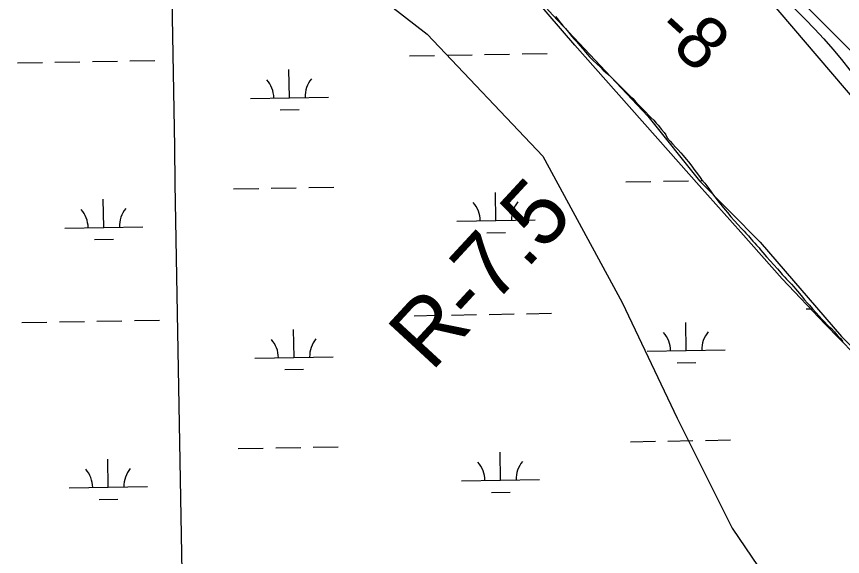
# Model space of a CAD drawing. Extents: x 3903937 to 3942190, y 260677 to 286651.
# Drawn here: x 3923778 to 3924835, y 275569 to 276260 of the extents above; entities that cross this region are included whole.
import ezdxf

# ---------------------------------------------------------------- set-up
doc = ezdxf.new("R2010")
doc.units = 0
for name, color, linetype in [('V-GRID-MAJR', 7, 'Continuous'), ('V-RIVR-EDGE', 7, 'Continuous'), ('V-RIVR-RANG', 7, 'Continuous'), ('V-RIVR-RANG-IDEN', 7, 'Continuous'), ('V-RRAP-FSHR', 7, 'Continuous'), ('V-SITE-VEGE', 7, 'Continuous'), ('V-TOPO-DPTH', 7, 'Continuous'), ('V-TOPO-MINR', 7, 'Continuous'), ('V-WETL-SWMP', 7, 'Continuous')]:
    doc.layers.add(name, color=color, linetype=linetype)

msp = doc.modelspace()

# ---------------------------------------------------------------- linework, layer by layer
at = {"layer": 'V-GRID-MAJR'}
msp.add_spline([(3924152.694, 266296.911), (3924046.094, 272353.359), (3923939.434, 278413.279), (3923832.773, 284473.19), (3923832.7120000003, 284476.667)], degree=3, dxfattribs=at)
at = {"layer": 'V-RIVR-EDGE'}
msp.add_lwpolyline([(3923809.041392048, 277077.51291171), (3923934.9847806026, 276930.5789583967), (3924022.0956243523, 276825.6261346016), (3924100.8102421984, 276726.9704802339), (3924229.9022154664, 276553.79832097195), (3924320.1616439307, 276432.0530453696), (3924352.6970193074, 276398.4681417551), (3924369.4894711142, 276368.03182285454), (3924377.885697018, 276353.33842752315), (3924399.9257900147, 276333.39739100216), (3924463.9470125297, 276262.0294708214), (3924585.692288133, 276132.93749755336), (3924651.8125671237, 276050.02476675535), (3924729.477656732, 275971.3101489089), (3924833.3809522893, 275850.6144015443), (3924912.0955701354, 275772.9493119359), (3925056.9304669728, 275630.21347157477), (3925314.0648852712, 275376.22763799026)], dxfattribs=at)
at = {"layer": 'V-RRAP-FSHR'}
msp.add_lwpolyline([(3924868.6260422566, 275809.15788427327), (3924812.6111942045, 275866.2745563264), (3924757.724794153, 275924.4418523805), (3924704.6262981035, 275984.2803164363), (3924651.527802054, 276044.11878049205), (3924598.431354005, 276103.95724454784), (3924545.3328579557, 276163.7957086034), (3924492.2343619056, 276223.6341726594), (3924439.8751938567, 276284.96972471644), (3924389.62136981, 276346.34214077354), (3924339.367545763, 276408.58905283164), (3924289.1137217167, 276470.83596488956), (3924238.8598976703, 276533.79967694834), (3924188.6060736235, 276595.3256930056), (3924138.3522495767, 276657.57260506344), (3924088.86028153, 276719.80722912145), (3924037.8015934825, 276782.28966117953), (3923987.5150014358, 276844.2498532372), (3923937.232505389, 276906.4701412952), (3923886.9479613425, 276968.6924773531), (3923836.661369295, 277030.91276541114), (3923777.9144892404, 277084.7342054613)], dxfattribs=at)
at = {"layer": 'V-SITE-VEGE'}
for p, q in [((3924123.8340000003, 276378.223), (3924303.3000000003, 276237.702)), ((3924303.3000000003, 276237.702), (3924451.557, 276081.56200000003)), ((3924451.557, 276081.56200000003), (3924552.9960000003, 275894.199)), ((3924552.9960000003, 275894.199), (3924623.222, 275745.869)), ((3924623.222, 275745.869), (3924693.448, 275605.34499999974)), ((3924693.448, 275605.34499999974), (3924810.494, 275433.594))]:
    msp.add_line(p, q, dxfattribs=at)
at = {"layer": 'V-TOPO-DPTH'}
for points in [[(3923865.174726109, 277116.27481425), (3923945.7666094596, 277041.54291989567), (3924026.2410626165, 276966.68508159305), (3924106.539370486, 276891.6383273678), (3924186.720248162, 276816.4656291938), (3924428.1951694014, 276589.5397381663), (3924477.5856964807, 276542.7901825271), (3924526.750617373, 276495.8062376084), (3924575.5771289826, 276448.47070877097), (3924624.178034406, 276400.90079065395), (3924719.8113720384, 276306.62193106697), (3924721.0372647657, 276305.40519470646), (3924721.64690651, 276304.79351949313), (3924722.2548959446, 276304.1801907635), (3924727.854134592, 276298.50879869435), (3924730.4768868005, 276295.7084617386), (3924731.727843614, 276294.25462085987), (3924734.086898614, 276291.2362584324), (3924736.08815973, 276287.99108001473), (3924736.9511130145, 276286.2835869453), (3925453.180204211, 275446.62080505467)], [(3925522.551794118, 275441.304044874), (3924958.2296571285, 276088.6577581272), (3924936.4956570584, 276115.5661055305), (3924914.136955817, 276141.944487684), (3924891.2998223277, 276167.8897105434), (3924867.745040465, 276193.1851944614), (3924843.711826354, 276218.04751908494), (3924757.4314059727, 276304.83790498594), (3924747.84406271, 276314.4520852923), (3924738.2369359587, 276324.04639421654), (3924728.6001339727, 276333.61089606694), (3924718.943548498, 276343.15552653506), (3924144.81338033, 276908.8740663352), (3924099.7941607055, 276953.09772132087), (3924054.6847673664, 276997.2289203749), (3924009.440113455, 277041.2214355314), (3923964.105285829, 277085.12149475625)], [(3923964.105285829, 277085.12149475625), (3924009.440113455, 277041.2214355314), (3924054.6847673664, 276997.2289203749), (3924099.7941607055, 276953.09772132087), (3924144.81338033, 276908.8740663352), (3924718.943548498, 276343.15552653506), (3924728.6001339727, 276333.61089606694), (3924738.2369359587, 276324.04639421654), (3924747.84406271, 276314.4520852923), (3924757.4314059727, 276304.83790498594), (3924843.711826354, 276218.04751908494), (3924867.745040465, 276193.1851944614), (3924891.2998223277, 276167.8897105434), (3924914.136955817, 276141.944487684), (3924936.4956570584, 276115.5661055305), (3924958.2296571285, 276088.6577581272), (3925522.551794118, 275441.304044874)]]:
    msp.add_lwpolyline(points, dxfattribs=at)
at = {"layer": 'V-TOPO-MINR'}
for points in [[(3923865.174726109, 277116.27481425), (3923945.7666094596, 277041.54291989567), (3924026.2410626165, 276966.68508159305), (3924106.539370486, 276891.6383273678), (3924186.720248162, 276816.4656291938), (3924428.1951694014, 276589.5397381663), (3924477.5856964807, 276542.7901825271), (3924526.750617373, 276495.8062376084), (3924575.5771289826, 276448.47070877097), (3924624.178034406, 276400.90079065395), (3924719.8113720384, 276306.62193106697), (3924721.0372647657, 276305.40519470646), (3924721.64690651, 276304.79351949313), (3924722.2548959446, 276304.1801907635), (3924727.854134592, 276298.50879869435), (3924730.4768868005, 276295.7084617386), (3924731.727843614, 276294.25462085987), (3924734.086898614, 276291.2362584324), (3924736.08815973, 276287.99108001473), (3924736.9511130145, 276286.2835869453), (3925453.180204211, 275446.62080505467)], [(3923964.105285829, 277085.12149475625), (3924009.440113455, 277041.2214355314), (3924054.6847673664, 276997.2289203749), (3924099.7941607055, 276953.09772132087), (3924144.81338033, 276908.8740663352), (3924718.943548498, 276343.15552653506), (3924728.6001339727, 276333.61089606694), (3924738.2369359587, 276324.04639421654), (3924747.84406271, 276314.4520852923), (3924757.4314059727, 276304.83790498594), (3924843.711826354, 276218.04751908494), (3924867.745040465, 276193.1851944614), (3924891.2998223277, 276167.8897105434), (3924914.136955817, 276141.944487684), (3924936.4956570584, 276115.5661055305), (3924958.2296571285, 276088.6577581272), (3925522.551794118, 275441.304044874)], [(3923968.4715438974, 277067.63885066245), (3923988.589107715, 277047.81587338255), (3924719.3890937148, 276325.1749291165), (3924724.581696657, 276320.02429766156), (3924729.7635768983, 276314.86293432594), (3924734.92937309, 276309.68547316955), (3924740.0844465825, 276304.4972801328), (3924787.0799062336, 276257.0524962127), (3924799.1076362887, 276244.5422939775), (3924810.8788639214, 276231.8020856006), (3924822.265337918, 276218.71686801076), (3924833.395309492, 276205.401644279), (3924844.1759246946, 276191.7960544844), (3924854.7480065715, 276178.0339731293), (3924865.007288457, 276164.037154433), (3925522.609775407, 275428.3667472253)]]:
    msp.add_lwpolyline(points, dxfattribs=at)
at = {"layer": 'V-WETL-SWMP'}
for p, q in [((3924467.392, 276260.395), (3924470.0640000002, 276257.286)), ((3924470.0640000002, 276257.286), (3924473.912, 276252.2489999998)), ((3924473.912, 276252.2489999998), (3924476.5840000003, 276249.1399999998)), ((3924476.5840000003, 276249.1399999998), (3924480.219, 276244.95899999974)), ((3924480.219, 276244.95899999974), (3924482.3570000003, 276242.386)), ((3924482.3570000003, 276242.386), (3924485.7770000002, 276238.098)), ((3924485.7770000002, 276238.098), (3924488.128, 276235.204)), ((3924488.128, 276235.204), (3924491.977, 276230.808)), ((3924491.977, 276230.808), (3924494.756, 276227.806)), ((3924494.756, 276227.806), (3924498.7120000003, 276223.089)), ((3924498.7120000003, 276223.08899999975), (3924502.881, 276218.37200000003)), ((3924376.7865008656, 276211.56158461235), (3924408.781544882, 276212.12475278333)), ((3924424.77906689, 276212.40633686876), (3924456.7741109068, 276212.96950503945)), ((3924502.881, 276218.37200000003), (3924505.66, 276215.049)), ((3924505.66, 276215.049), (3924508.4390000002, 276211.832)), ((3924508.4390000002, 276211.832), (3924511.325, 276208.509)), ((3923778.9711015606, 276201.0389985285), (3923810.9661455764, 276201.6021666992)), ((3923826.9636675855, 276201.8837507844), (3923858.9587116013, 276202.4469189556)), ((3923874.95623361, 276202.7285030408), (3923906.951277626, 276203.2916712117)), ((3923922.948799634, 276203.5732552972), (3923954.943843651, 276204.1364234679)), ((3924280.8013688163, 276209.87208010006), (3924312.7964128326, 276210.43524827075)), ((3924328.793934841, 276210.716832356), (3924360.788978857, 276211.28000052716)), ((3924511.325, 276208.5089999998), (3924516.244, 276203.684)), ((3924516.244, 276203.684), (3924519.88, 276200.252)), ((3924127.1263199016, 276156.4172733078), (3924126.4927557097, 276192.4116978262)), ((3924519.88, 276200.252), (3924525.2260000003, 276195.319)), ((3924525.2260000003, 276195.319), (3924528.755, 276191.888)), ((3924528.755, 276191.888), (3924534.2090000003, 276187.06200000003)), ((3924534.2090000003, 276187.06200000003), (3924539.234, 276182.34299999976)), ((3924539.234, 276182.34299999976), (3924542.335, 276179.23399999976)), ((3924542.335, 276179.234), (3924546.826, 276174.6229999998)), ((3924546.826, 276174.6229999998), (3924549.819, 276171.62099999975)), ((3924549.819, 276171.62099999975), (3924554.524, 276166.90299999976)), ((3924554.524, 276166.903), (3924557.839, 276163.686)), ((3924557.839, 276163.686), (3924562.971, 276158.539)), ((3924077.134063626, 276155.53732304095), (3924177.118576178, 276157.29722357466)), ((3924562.971, 276158.539), (3924566.392, 276155.215)), ((3924566.392, 276155.215), (3924569.4930000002, 276151.998)), ((3924569.4930000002, 276151.998), (3924573.876, 276147.281)), ((3924115.3997486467, 276140.77747511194), (3924139.396031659, 276141.1998512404)), ((3924573.876, 276147.281), (3924576.656, 276144.4929999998)), ((3924576.656, 276144.4929999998), (3924580.612, 276140.418)), ((3924580.612, 276140.418), (3924583.071, 276137.84500000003)), ((3924583.071, 276137.84500000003), (3924587.134, 276133.7709999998)), ((3924587.134, 276133.7709999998), (3924589.593, 276131.197)), ((3924589.593, 276131.197), (3924593.228, 276127.4439999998)), ((3924593.228, 276127.4439999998), (3924596.542, 276123.692)), ((3924596.542, 276123.692), (3924598.787, 276121.2259999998)), ((3924598.787, 276121.2259999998), (3924603.2770000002, 276115.866)), ((3924603.2770000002, 276115.866), (3924606.483, 276111.68599999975)), ((3924606.483, 276111.68599999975), (3924608.728, 276108.7919999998)), ((3924608.728, 276108.7919999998), (3924610.543, 276105.148)), ((3924610.543, 276105.148), (3924614.498, 276100.753)), ((3924614.498, 276100.753), (3924617.384, 276097.536)), ((3924617.384, 276097.536), (3924621.447, 276092.81900000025)), ((3924621.447, 276092.8189999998), (3924624.2260000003, 276090.0309999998)), ((3924624.2260000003, 276090.0309999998), (3924628.075, 276085.63599999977)), ((3924628.075, 276085.63599999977), (3924630.8540000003, 276082.52699999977)), ((3924630.8540000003, 276082.52699999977), (3924634.702, 276077.81)), ((3924634.702, 276077.81), (3924637.588, 276074.27299999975)), ((3924637.588, 276074.27299999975), (3924641.863, 276068.592)), ((3924641.863, 276068.592), (3924644.7490000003, 276064.8399999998)), ((3924644.7490000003, 276064.8399999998), (3924647.5270000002, 276061.088)), ((3924647.5270000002, 276061.088), (3924651.802, 276055.514)), ((3924651.802, 276055.514), (3924654.474, 276051.87)), ((3924557.5914445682, 276048.5443245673), (3924589.5864885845, 276049.107492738)), ((3924605.5840105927, 276049.3890768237), (3924637.5790546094, 276049.9522449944)), ((3924653.5765766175, 276050.2338290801), (3924655.7897350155, 276050.2727844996)), ((3924654.474, 276051.87), (3924658.5360000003, 276046.9389999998)), ((3924658.5360000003, 276046.9389999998), (3924661.1010000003, 276043.61599999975)), ((3924661.1010000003, 276043.61599999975), (3924664.413, 276039.007)), ((3924055.7611773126, 276039.71124299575), (3924087.756221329, 276040.27441116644)), ((3924103.7537433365, 276040.55599525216), (3924135.7487873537, 276041.11916342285)), ((3924151.7463093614, 276041.4007475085), (3924183.7413533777, 276041.96391567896)), ((3924391.3704403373, 275999.1813551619), (3924390.7368761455, 276035.1757796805)), ((3924664.413, 276039.007), (3924666.765, 276035.89900000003)), ((3924666.765, 276035.89900000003), (3924669.864, 276031.718)), ((3923889.5401730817, 275990.3482735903), (3923888.90660889, 276026.3426981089)), ((3924669.864, 276031.718), (3924673.0700000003, 276027.324)), ((3924673.0700000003, 276027.324), (3924675.3140000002, 276024.215)), ((3924675.3140000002, 276024.215), (3924678.52, 276020.03500000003)), ((3924678.52, 276020.03500000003), (3924680.6580000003, 276017.46199999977)), ((3924680.6580000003, 276017.46199999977), (3924684.72, 276012.638)), ((3924684.72, 276012.638), (3924687.4990000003, 276009.315)), ((3924687.4990000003, 276009.31499999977), (3924692.096, 276003.9539999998)), ((3924692.096, 276003.9539999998), (3924696.6920000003, 275998.8079999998)), ((3923839.5479168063, 275989.46832332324), (3923939.5324293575, 275991.22822385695)), ((3924341.378184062, 275998.30140489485), (3924441.362696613, 276000.0613054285)), ((3924696.6920000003, 275998.8079999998), (3924701.076, 275993.984)), ((3924701.076, 275993.984), (3924705.6720000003, 275988.731)), ((3924379.6438690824, 275983.5415569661), (3924403.640152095, 275983.9639330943)), ((3924705.6720000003, 275988.731), (3924708.88, 275985.3)), ((3924708.88, 275985.3), (3924711.018, 275983.155)), ((3924711.018, 275983.155), (3924714.332, 275979.403)), ((3924714.332, 275979.403), (3924717.967, 275975.43599999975)), ((3923877.813601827, 275974.70847539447), (3923901.809884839, 275975.13085152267)), ((3924717.967, 275975.43599999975), (3924720.2120000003, 275972.8629999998)), ((3924720.2120000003, 275972.863), (3924722.457, 275970.28999999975)), ((3924722.457, 275970.28999999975), (3924724.809, 275967.717)), ((3924724.809, 275967.717), (3924728.122, 275963.9649999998)), ((3924728.122, 275963.9649999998), (3924730.046, 275961.499)), ((3924730.046, 275961.499), (3924733.039, 275958.068)), ((3924733.039, 275958.068), (3924737.7430000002, 275952.815)), ((3924737.7430000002, 275952.815), (3924742.233, 275947.669)), ((3924742.233, 275947.669), (3924747.044, 275942.309)), ((3924747.044, 275942.309), (3924751.5330000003, 275937.056)), ((3924751.5330000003, 275937.056), (3924754.2060000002, 275934.161)), ((3924754.2060000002, 275934.161), (3924757.734, 275930.087)), ((3924757.734, 275930.087), (3924760.8340000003, 275926.549)), ((3924760.8340000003, 275926.549), (3924763.186, 275924.18999999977)), ((3924763.186, 275924.18999999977), (3924767.035, 275920.223)), ((3924767.035, 275920.223), (3924769.494, 275917.65)), ((3924769.494, 275917.65), (3924772.594, 275914.112)), ((3924772.594, 275914.112), (3924774.625, 275911.86)), ((3924774.625, 275911.86), (3924777.2970000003, 275908.5369999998)), ((3924777.2970000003, 275908.5369999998), (3924781.894, 275903.0699999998)), ((3924781.894, 275903.0699999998), (3924786.383, 275897.603)), ((3924786.383, 275897.603), (3924789.9110000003, 275893.422)), ((3924788.4863851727, 275886.0816845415), (3924796.250897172, 275886.21835339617)), ((3924789.9110000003, 275893.422), (3924792.369, 275890.7419999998)), ((3924792.369, 275890.7419999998), (3924796.325, 275886.132)), ((3924796.325, 275886.132), (3924800.494, 275881.30699999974)), ((3924286.656117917, 275877.24860297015), (3924318.6511619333, 275877.81177114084)), ((3924334.648683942, 275878.09335522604), (3924366.643727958, 275878.6565233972)), ((3924382.641249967, 275878.93810748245), (3924414.6362939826, 275879.50127565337)), ((3924430.633815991, 275879.78285973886), (3924462.6288600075, 275880.34602790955)), ((3924800.494, 275881.30699999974), (3924804.877, 275876.483)), ((3924804.877, 275876.483), (3924808.9390000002, 275872.194)), ((3923784.8258506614, 275868.41552139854), (3923816.8208946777, 275868.9786895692)), ((3923832.8184166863, 275869.2602736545), (3923864.8134607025, 275869.82344182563)), ((3923880.810982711, 275870.1050259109), (3923912.806026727, 275870.6681940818)), ((3923928.803548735, 275870.94977816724), (3923960.7985927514, 275871.5129463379)), ((3924634.8113362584, 275832.62687774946), (3924634.177772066, 275868.62130226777)), ((3924808.9390000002, 275872.194), (3924811.826, 275869.299)), ((3924811.826, 275869.299), (3924815.355, 275865.65299999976)), ((3924815.355, 275865.65299999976), (3924817.4930000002, 275863.40199999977)), ((3924817.4930000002, 275863.40199999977), (3924820.541, 275860.667)), ((3924132.9810690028, 275823.7937961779), (3924132.3475048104, 275859.7882206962)), ((3924820.541, 275860.667), (3924824.657, 275856.593)), ((3924824.657, 275856.593), (3924826.794, 275853.431)), ((3924826.794, 275853.431), (3924829.894, 275850.107)), ((3924829.894, 275850.107), (3924832.0330000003, 275847.85499999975)), ((3924832.0330000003, 275847.85499999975), (3924835.24, 275844.42399999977)), ((3924584.819079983, 275831.7469274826), (3924684.8035925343, 275833.5068280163)), ((3924082.988812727, 275822.91384591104), (3924182.973325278, 275824.6737464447)), ((3924623.084765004, 275816.9870795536), (3924647.0810480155, 275817.40945568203)), ((3924121.254497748, 275808.15399798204), (3924145.25078076, 275808.5763741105)), ((3924563.4461936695, 275715.9208474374), (3924595.441237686, 275716.4840156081)), ((3924611.4387596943, 275716.76559969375), (3924643.43380371, 275717.3287678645)), ((3924659.4313257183, 275717.61035195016), (3924691.426369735, 275718.1735201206)), ((3924061.615926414, 275707.0877658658), (3924093.6109704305, 275707.6509340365)), ((3924109.608492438, 275707.9325181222), (3924141.6035364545, 275708.4956862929)), ((3924157.6010584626, 275708.7772703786), (3924189.596102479, 275709.34043854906)), ((3923895.394922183, 275657.7247964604), (3923894.7613579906, 275693.71922097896)), ((3924397.225189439, 275666.557878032), (3924396.591625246, 275702.5523025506)), ((3924347.232933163, 275665.6779277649), (3924447.217445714, 275667.4378282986)), ((3923845.4026659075, 275656.84484619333), (3923945.3871784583, 275658.604746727)), ((3923883.6683509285, 275642.08499826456), (3923907.66463394, 275642.50737439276)), ((3924385.498618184, 275650.9180798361), (3924409.4949011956, 275651.3404559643))]:
    msp.add_line(p, q, dxfattribs=at)
for centre, radius, start, end in [((3924182.352344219, 276157.86422368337), 35.24628790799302, 140.23657772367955, 181.78023605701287), ((3924071.883583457, 276155.9197822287), 35.24628790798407, 0.23658072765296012, 41.78023906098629), ((3924336.1277038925, 275998.68386408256), 35.24628790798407, 0.23658072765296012, 41.78023906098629), ((3924446.5964646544, 276000.62830553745), 35.24628790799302, 140.23657772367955, 181.78023605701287), ((3923834.2974366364, 275989.850782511), 35.24628790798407, 0.23658072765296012, 41.78023906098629), ((3923944.766197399, 275991.7952239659), 35.24628790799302, 140.23657772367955, 181.78023605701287), ((3924579.5685998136, 275832.12938667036), 35.24628790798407, 0.23658072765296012, 41.78023906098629), ((3924690.037360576, 275834.073828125), 35.24628790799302, 140.23657772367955, 181.78023605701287), ((3924077.738332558, 275823.2963050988), 35.24628790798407, 0.23658072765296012, 41.78023906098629), ((3924188.20709332, 275825.2407465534), 35.24628790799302, 140.23657772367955, 181.78023605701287), ((3924341.9824529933, 275666.06038695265), 35.24628790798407, 0.23658072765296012, 41.78023906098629), ((3924452.4512137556, 275668.00482840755), 35.24628790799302, 140.23657772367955, 181.78023605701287), ((3923840.1521857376, 275657.2273053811), 35.24628790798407, 0.23658072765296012, 41.78023906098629), ((3923950.6209465, 275659.1717468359), 35.24628790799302, 140.23657772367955, 181.78023605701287)]:
    msp.add_arc(centre, radius, start, end, dxfattribs=at)

# ---------------------------------------------------------------- texts
at = {"layer": 'V-RIVR-RANG'}
msp.add_text('-8', height=67, rotation=317.43905555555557, dxfattribs=at).set_placement((3924592.6698477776, 276239.6994724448))
at = {"layer": 'V-RIVR-RANG-IDEN'}
msp.add_text('R-7.5', height=82.99999799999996, rotation=47.2974527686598, dxfattribs=at).set_placement((3924308.8198730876, 275804.24895154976))

doc.saveas('drawing.dxf')
